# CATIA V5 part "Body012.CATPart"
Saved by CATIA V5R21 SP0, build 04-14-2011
Part number: Body012
Definition: design
Nomenclature: Body012
Source: Unknown
Bounding box of the stored display mesh (mm): x -0.35 to 0.35, y -1.5 to 1.5, z 0 to 0.1
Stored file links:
  C:\Users\beatr\OneDrive\Documents\UNB\2026_1\Pi1\Componentes eletronicos\Encoder\Body012.CATPart
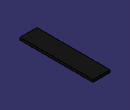
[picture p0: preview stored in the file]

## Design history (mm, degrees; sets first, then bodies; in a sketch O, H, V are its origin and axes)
Body1 "MANIFOLD_SOLID_BREP #5447" (main body)
  Solid1: solid without history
